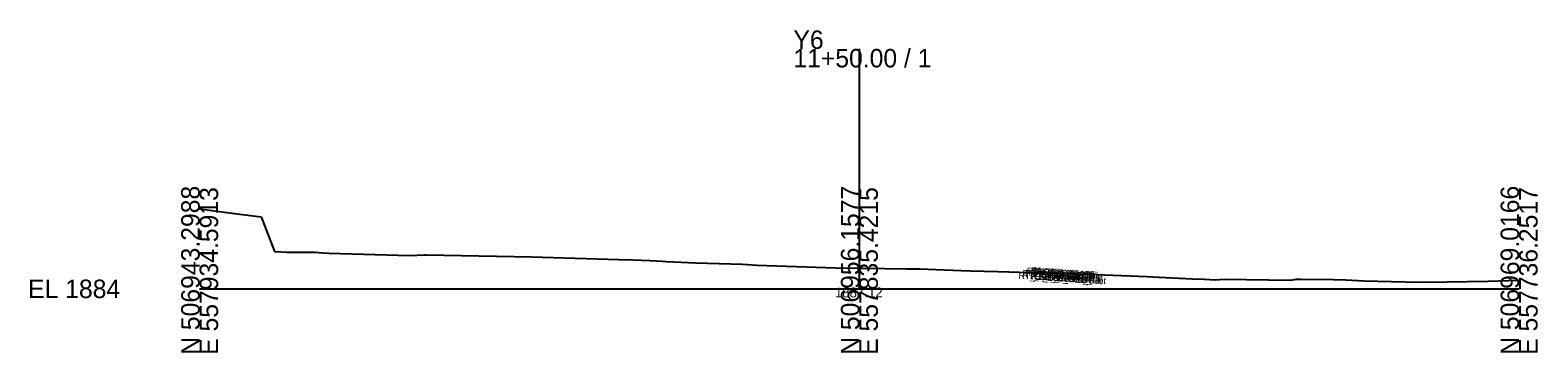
# Model space of a CAD drawing. Extents: x -26 to 203, y -10 to 1539.
# Drawn here: x -25.7 to 202.8, y 1490.3 to 1539.2 of the extents above; entities that cross this region are included whole.
import ezdxf

# ---------------------------------------------------------------- set-up
doc = ezdxf.new("R2010")
doc.units = 0
for name, color, linetype in [('Default', 7, 'Continuous'), ('Exist Cross Section Cell', 7, 'Continuous'), ('Exist XS Center Line Elevation Label', 7, 'Continuous'), ('Exist XS Ground Line', 7, 'Continuous'), ('Typical Text Asphalt at Bridge Approach CELL', 7, 'Continuous')]:
    doc.layers.add(name, color=color, linetype=linetype)

msp = doc.modelspace()

# ---------------------------------------------------------------- linework, layer by layer
at = {"layer": 'Exist Cross Section Cell'}
for p, q in [((100, 1500), (100, 1536.34)), ((0, 1500), (100, 1500)), ((100, 1500), (200, 1500))]:
    msp.add_line(p, q, dxfattribs=at)
at = {"layer": 'Exist XS Ground Line'}
for p, q in [((0, 1512.11), (5.67, 1511.38)), ((5.67, 1511.38), (9.3, 1510.92)), ((9.3, 1510.92), (11.32, 1505.64)), ((11.32, 1505.64), (12.33, 1505.6)), ((12.33, 1505.6), (13.23, 1505.56)), ((13.23, 1505.56), (13.57, 1505.57)), ((13.57, 1505.57), (16.22, 1505.56)), ((16.22, 1505.56), (17.52, 1505.54)), ((17.52, 1505.54), (18.63, 1505.47)), ((18.63, 1505.47), (19.58, 1505.42)), ((19.58, 1505.42), (31.85, 1505.06)), ((31.85, 1505.06), (34.02, 1505.14)), ((34.02, 1505.14), (34.36, 1505.13)), ((34.36, 1505.13), (50.28, 1504.83)), ((50.28, 1504.83), (63.53, 1504.44)), ((63.53, 1504.44), (65.69, 1504.39)), ((65.69, 1504.39), (68.22, 1504.31)), ((68.22, 1504.31), (70.15, 1504.2)), ((70.15, 1504.2), (70.71, 1504.16)), ((70.71, 1504.16), (75.23, 1503.96)), ((75.23, 1503.96), (82.29, 1503.72)), ((82.29, 1503.72), (84.53, 1503.58)), ((84.53, 1503.58), (88.95, 1503.44)), ((88.95, 1503.44), (90.49, 1503.36)), ((90.49, 1503.36), (94.92, 1503.25)), ((94.92, 1503.25), (96.39, 1503.19)), ((96.39, 1503.19), (99.67, 1503.13)), ((99.67, 1503.13), (100, 1503.12)), ((100, 1503.12), (100.45, 1503.11)), ((100.45, 1503.11), (107.19, 1503.02)), ((107.19, 1503.02), (107.69, 1503.01)), ((107.69, 1503.01), (109.11, 1503.01)), ((109.11, 1503.01), (114.15, 1502.83)), ((114.15, 1502.83), (115.44, 1502.79)), ((115.44, 1502.79), (116.83, 1502.75)), ((116.83, 1502.75), (121.03, 1502.62)), ((121.03, 1502.62), (125.85, 1502.48)), ((125.85, 1502.48), (128.97, 1502.4)), ((128.97, 1502.4), (134.56, 1502.23)), ((134.56, 1502.23), (143.62, 1501.85)), ((143.62, 1501.85), (144.41, 1501.8)), ((144.41, 1501.8), (150.51, 1501.53)), ((150.51, 1501.53), (152.32, 1501.45)), ((152.32, 1501.45), (153.95, 1501.38)), ((153.95, 1501.38), (155.27, 1501.45)), ((155.27, 1501.45), (165.38, 1501.33)), ((165.38, 1501.33), (166.23, 1501.45)), ((166.23, 1501.45), (166.98, 1501.44)), ((166.98, 1501.44), (171.89, 1501.4)), ((171.89, 1501.4), (173.72, 1501.35)), ((173.72, 1501.35), (176.47, 1501.19)), ((176.47, 1501.19), (184.86, 1501.03)), ((184.86, 1501.03), (189.04, 1501.04)), ((189.04, 1501.04), (195.26, 1501.16)), ((195.26, 1501.16), (200, 1501.29))]:
    msp.add_line(p, q, dxfattribs=at)

# ---------------------------------------------------------------- texts
at = {"layer": 'Default'}
msp.add_text('-', height=0.0001, dxfattribs=at).set_placement((0, 1500))
at = {"layer": 'Exist Cross Section Cell'}
for s, p in [('Y6', (90, 1536.34)), ('11+50.00 / 1', (90, 1533.54)), ('EL 1884', (-26, 1498.6))]:
    msp.add_text(s, height=2.8, dxfattribs=at).set_placement(p)
for s, p in [('N 506943.2988', (0, 1490)), ('E 557934.5913', (2.8, 1490)), ('N 506956.1577', (100, 1490)), ('E 557835.4215', (102.8, 1490)), ('N 506969.0166', (200, 1490)), ('E 557736.2517', (202.8, 1490))]:
    msp.add_text(s, height=2.8, rotation=90, dxfattribs=at).set_placement(p)
at = {"layer": 'Exist XS Center Line Elevation Label'}
msp.add_text('1887.12', height=1.5, dxfattribs=at).set_placement((96.29, 1498.7))
at = {"layer": 'Typical Text Asphalt at Bridge Approach CELL'}
for s, p in [('RT_Sub_Trench_Out', (124.09, 1501.56)), ('RT_Sub_Trench_Out', (124.66, 1501.61)), ('RT_PS3_Shelf_Out', (124.7, 1501.89)), ('RT_PS3_Shelf_Out', (125.11, 1501.93)), ('RT_GS_OS_CTL', (125.34, 1502.24)), ('RT_PV2_OEOT', (125.93, 1502.07)), ('RT_PV3_OEOT', (125.93, 1501.82)), ('RT_PS3_OEOP', (125.93, 1501.8)), ('RT_Sub_OEOT', (125.96, 1501.45)), ('RT_PS2_OEOP', (125.98, 1502.04)), ('RT_PV2_OEOT', (125.99, 1502.04)), ('RT_PV3_OEOT', (125.99, 1501.79)), ('RT_Sub_OEOT', (126.02, 1501.41)), ('RT_PS2_OEOP', (126.04, 1502.08)), ('RT_PV1_OEOT', (126.05, 1502.32)), ('RT_PS1_OEOP', (126.09, 1502.31)), ('RT_PS3_OEOP', (126.1, 1501.84)), ('RT_PV1_OEOT', (126.11, 1502.28)), ('RT_PS1_OEOP', (126.15, 1502.28)), ('RT_GS_OS_CTL', (126.16, 1502.29)), ('RT_Slope_Cut', (126.88, 1502.12)), ('11+06.62', (127.16, 1502.23)), ('11+11.00', (127.46, 1502.2)), ('11+11.95', (127.5, 1502.2)), ('11+17.29', (127.52, 1502.19)), ('11+23.00', (127.58, 1502.19)), ('11+22.63', (127.59, 1502.19)), ('11+21.00', (127.63, 1502.18))]:
    msp.add_text(s, height=1, rotation=356, dxfattribs=at).set_placement(p)

doc.saveas('drawing.dxf')
